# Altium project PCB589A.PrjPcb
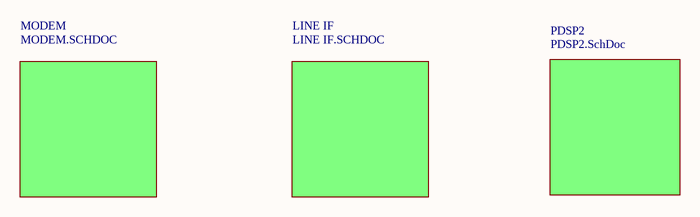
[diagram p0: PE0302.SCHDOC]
AAProductName: PE0302-; AABoardName: PCB589A
5 sheets, 127 parts. Net scope: flat (ports and power ports of the same name join across sheets).
Board file: PCB589A.PcbDoc
Sheets:
  FS.SchDoc
  PE0302.SCHDOC
    MODEM = MODEM.SCHDOC
    LINE IF = LINE IF.SCHDOC
    PDSP2 = PDSP2.SchDoc

## Sheet FS.SchDoc
size A3; Author: A.A.; Organization: CML Microcircuits UK Ltd; Address1: Oval Park, Langford; Address2: Maldon, Essex; Address3: CM9 6WG, England; DocumentNumber: 1; Revision: A01; SheetNumber: 1; SheetTotal: 5; FSProduct: PE0302; FSIPRDate: 2014; FSUM: UM/0302/1; FSDate: Dec 2014

## Sheet PE0302.SCHDOC: PE0302 - PDSP2 Evaluation Board
size A2; Date: /04/2011; DrawnBy: PB; Engineer: PB; Revision: A.01; SheetNumber: 5; SheetTotal: 5; ModifiedBy: PB; ProjectNo: 589

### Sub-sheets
LINE IF = LINE IF.SCHDOC: no entries
MODEM = MODEM.SCHDOC: no entries
PDSP2 = PDSP2.SchDoc: no entries

## Sheet MODEM.SCHDOC: PE0302 - PDSP2 Evaluation Board
size A2; Date: /04/2011; DrawnBy: PB; Engineer: PB; Organization: CML Microcircuits UK Ltd; Address1: Oval Park, Langford; Address2: Maldon, Essex; Address3: CM9 6WG, England; DocumentNumber: 2; Revision: A.01; SheetNumber: 2; SheetTotal: 5; ModifiedBy: PB; ProjectNo: 589
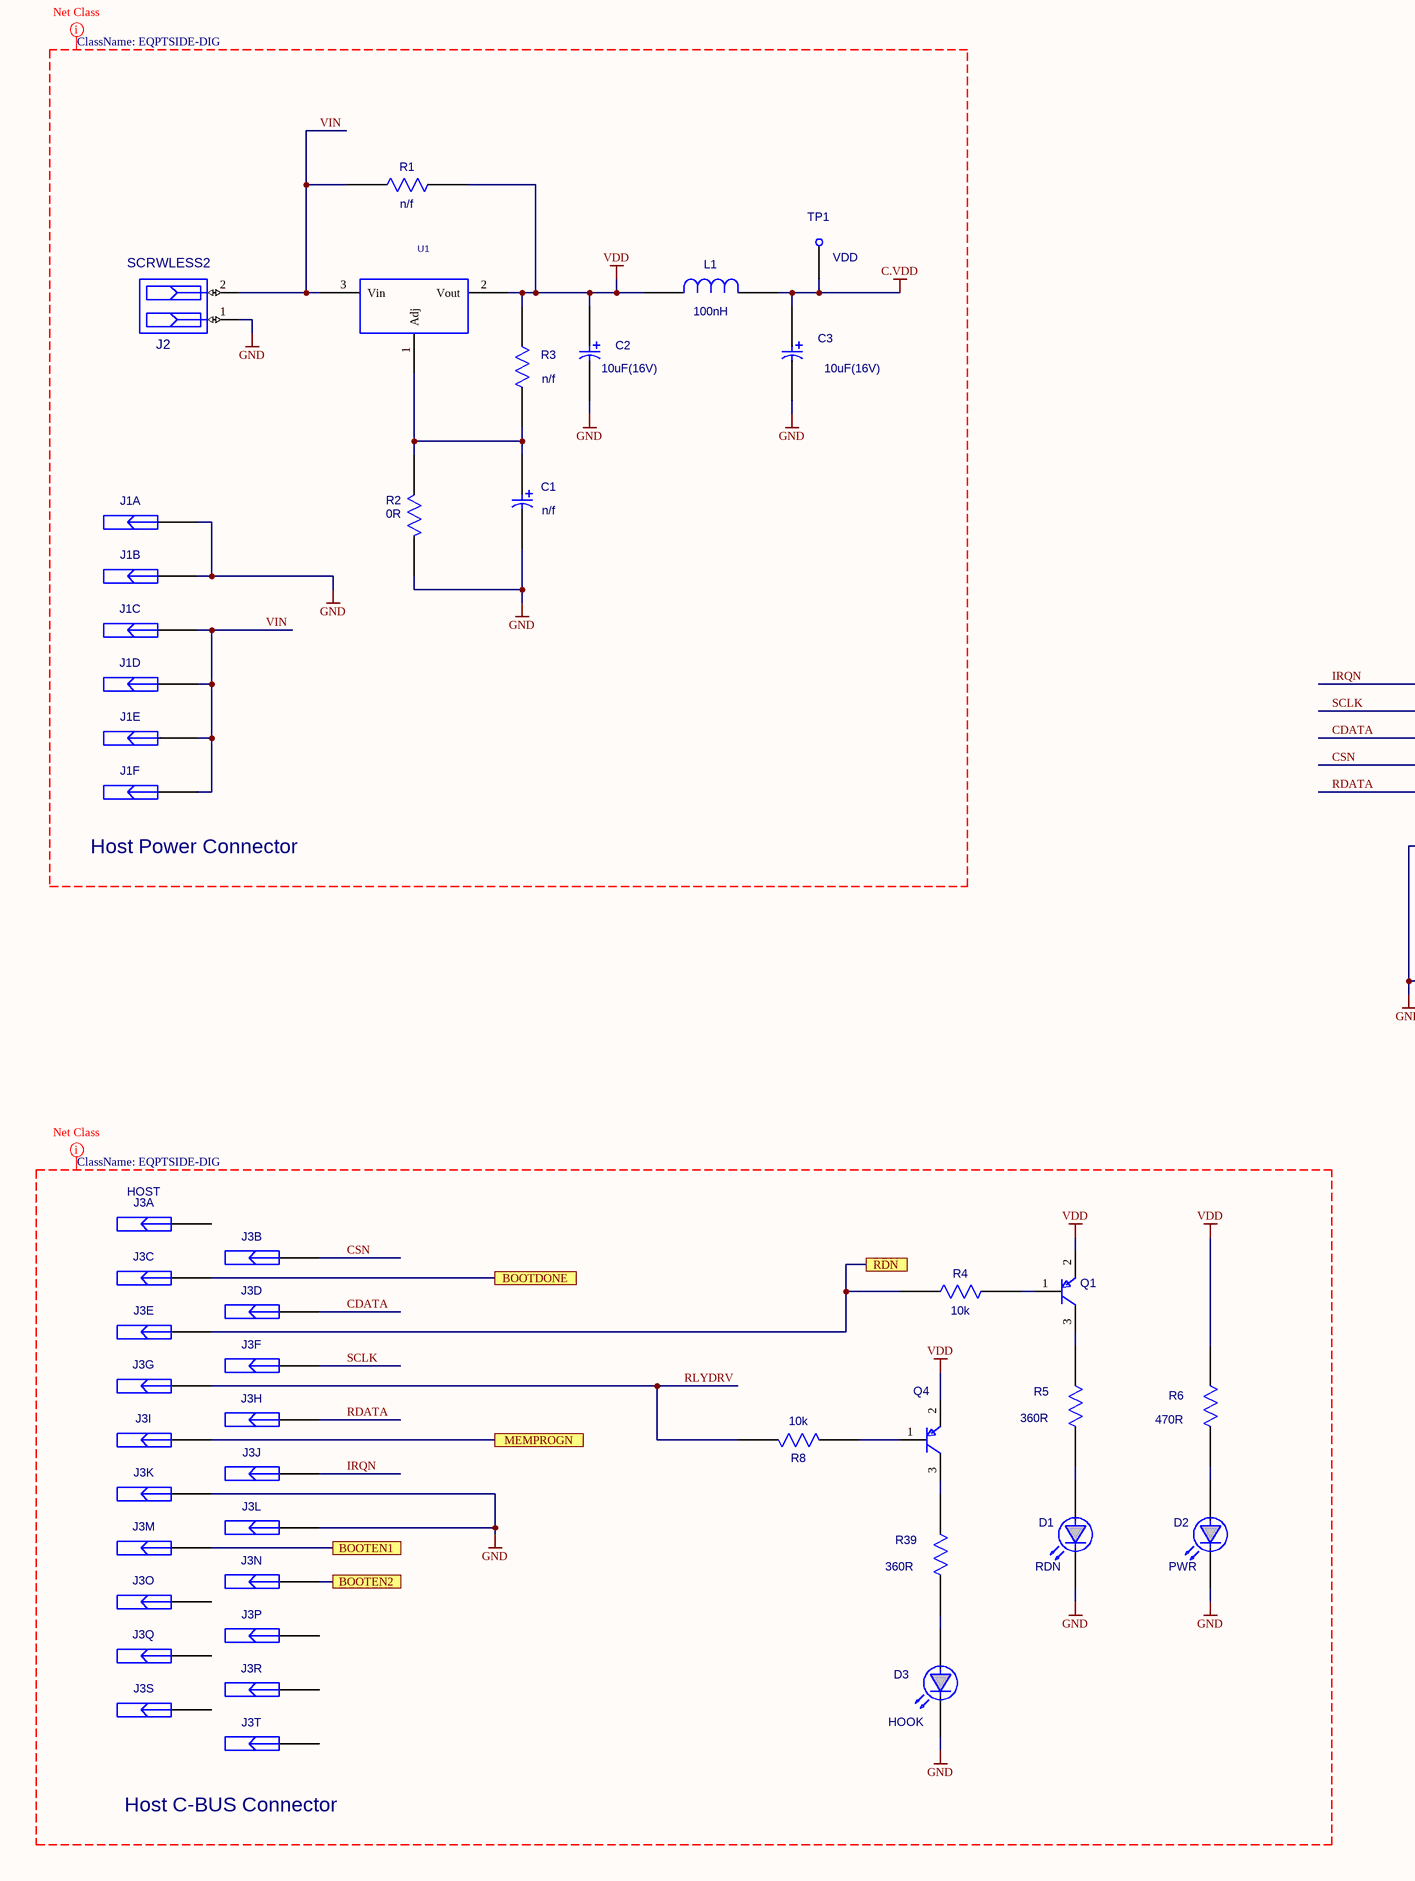
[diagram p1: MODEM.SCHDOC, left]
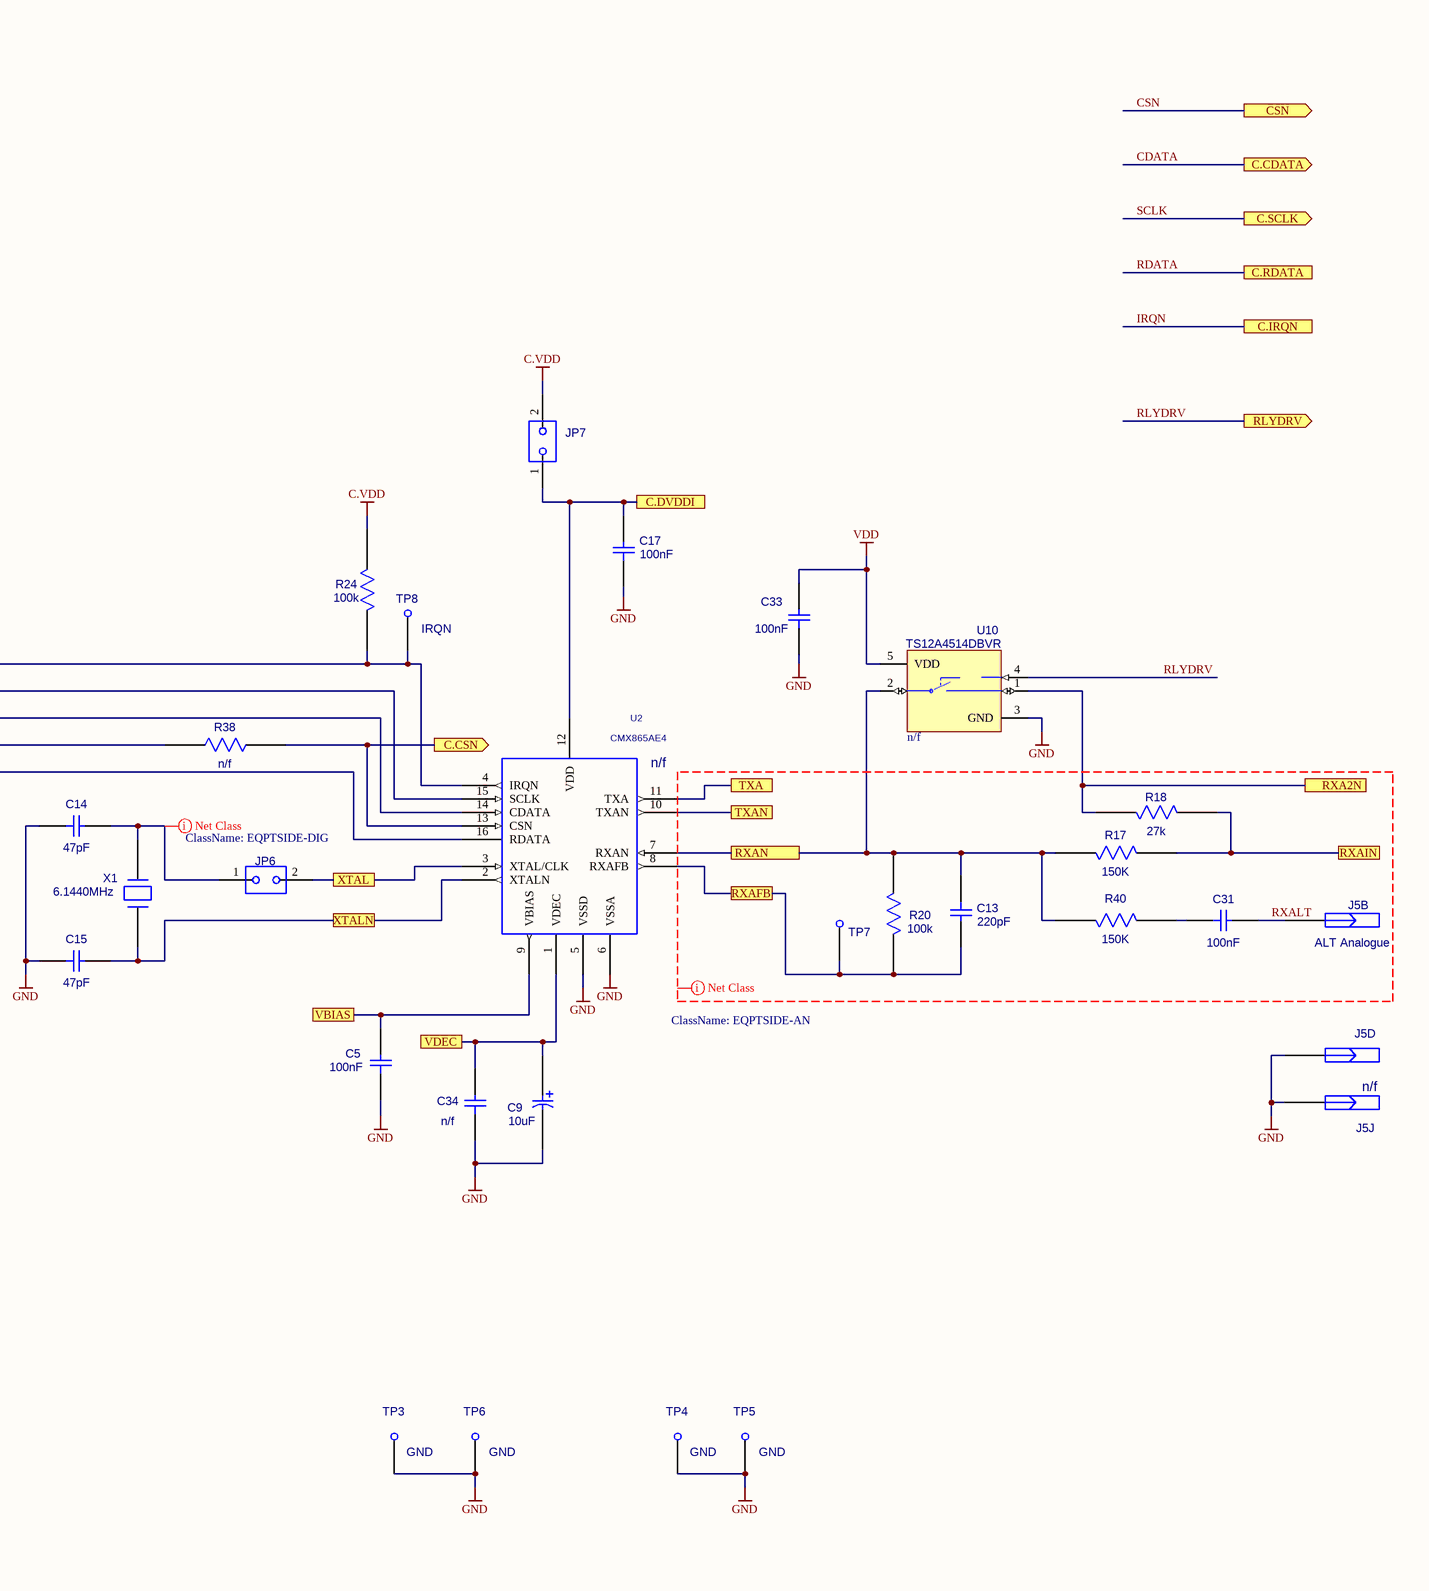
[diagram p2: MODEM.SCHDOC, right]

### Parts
C1  n/f  [TC3528P_CAP_TANT_TAJ_B(Primary)]
C2  10uF(16V)  [TC3528P_CAP_TANT_TAJ_B(Primary)]
C3  10uF(16V)  [TC3528P_CAP_TANT_TAJ_B(Primary)]
C5  100nF  [0603COM]
C9  10uF  [TC3528P_CAP_TANT_TAJ_B(Primary)]
C13  220pF  [0603COM]
C14  47pF  [0603COM]
C15  47pF  [0603COM]
C17  100nF  [0603COM]
C31  100nF  [0603COM]
C33  100nF  [0603COM]
C34  n/f  [0603COM]
D1  RDN  [LED0805]
D2  PWR  [LED0805]
D3  HOOK  [LED0805]
J1  (no value)  [IDC6RM]  (parts A,B,C,D,E,F of 6)
J2  SCRWLESS2  [SCRWLESS_2]
J3  HOST  [IDC20RM]  (parts A,B,C,D,E,F,G,H,I,J,K,L,M,N,O,P,Q,R,S,T of 20)
J5  ALT Analogue  [IDC10M]  (parts B,D,J of 10)
JP6  (no value)  [JMP2]
JP7  (no value)  [JMP2]
L1  100nH  [RC0805]
Q1  (no value)  [SOT-23]
Q4  (no value)  [SOT-23]
R1  n/f  [RC0805]
R2  0R  [0603COM]
R3  n/f  [RC0805]
R4  10k  [0603COM]
R5  360R  [0603COM]
R6  470R  [0603COM]
R8  10k  [0603COM]
R17  150K  [0603COM]
R18  27k  [0603COM]
R20  100k  [0603COM]
R24  100k  [0603COM]
R38  n/f  [0603COM]
R39  360R  [0603COM]
R40  150K  [0603COM]
TP1  VDD  [FISH_BEAD_FOOT_FISH_BEAD(Primary)]
TP3  GND  [FISH_BEAD_FOOT_FISH_BEAD(Primary)]
TP4  GND  [FISH_BEAD_FOOT_FISH_BEAD(Primary)]
TP5  GND  [FISH_BEAD_FOOT_FISH_BEAD(Primary)]
TP6  GND  [FISH_BEAD_FOOT_FISH_BEAD(Primary)]
TP7  RXAFB  [FISH_BEAD_FOOT_FISH_BEAD(Primary)]  (value not drawn)
TP8  IRQN  [FISH_BEAD_FOOT_FISH_BEAD(Primary)]
U1  (no value)  [TO-252]
U2  CMX865AE4  value n/f  [E4]
U10  TS12A4514DBVR  value n/f  [SOT23-5]
X1  6.1440MHz  [HC49]

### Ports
BOOTDONE, BOOTEN1, BOOTEN2, C.CDATA (out), C.CSN (out), C.DVDDI, C.IRQN, C.RDATA, C.SCLK (out), CSN (out), MEMPROGN, RDN, RLYDRV (out), RXA2N, RXAFB, RXAIN, RXAN, TXA, TXAN, VBIAS, VDEC, XTAL, XTALN

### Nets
C.VDD: C3.A(+ve) JP7.2 L1.1 R24.1 TP1.TP
GND: C1.B(-ve) C2.B(-ve) C3.B(-ve) C5.1 C9.B(-ve) C14.1 C15.1 C17.1 C33.1 C34.1 D1.2(CATHODE) D2.2(CATHODE) D3.2(CATHODE) J1.1 J1.2 J2.1 J3.11 J3.12 J5.4(P1) J5.10(P1) R2.1 TP3.TP TP4.TP TP5.TP TP6.TP U2.5(VSSD) U2.6(VSSA) U10.3(GND)
VDD: C2.A(+ve) C33.2 L1.2 Q1.2(E) Q4.2(E) R1.2 R3.2 R6.2 U1.2(Vout) U10.5(VDD)
BOOTDONE: J3.3 ; port BOOTDONE
BOOTEN1: J3.13 ; port BOOTEN1
BOOTEN2: J3.14 ; port BOOTEN2
C.CSN: R38.2 U2.13(CSN) ; port C.CSN
C.DVDDI: C17.2 JP7.1 U2.12(VDD) ; port C.DVDDI
CDATA: J3.4 U2.14(CDATA) ; port C.CDATA
CSN: J3.2 R38.1 ; port CSN
IRQN: J3.10 R24.2 TP8.TP U2.4(IRQN) ; port C.IRQN
MEMPROGN: J3.9 ; port MEMPROGN
NET00027: R18.2 U10.1(COM) ; port RXA2N
RDATA: J3.8 U2.16(RDATA) ; port C.RDATA
RDN: J3.5 R4.1 ; port RDN
RLYDRV: J3.7 R8.1 U10.4(IN) ; port RLYDRV
RXAFB: C13.2 R20.2 TP7.TP U2.8(RXAFB) ; port RXAFB
RXAIN: R17.1 R18.1 ; port RXAIN
RXALT: C31.2 J5.2(P1)
RXAN: C13.1 R17.2 R20.1 R40.2 U2.7(RXAN) U10.2(NO) ; port RXAN
SCLK: J3.6 U2.15(SCLK) ; port C.SCLK
TXA: U2.11(TXA) ; port TXA
TXAN: U2.10(TXAN) ; port TXAN
VBIAS: C5.2 U2.9(VBIAS) ; port VBIAS
VDEC: C9.A(+ve) C34.2 U2.1(VDEC) ; port VDEC
VIN: J1.3 J1.4 J1.5 J1.6 J2.2 R1.1 U1.3(Vin)
XTAL: JP6.2 U2.3(XTAL/CLK) ; port XTAL
XTALN: C15.2 U2.2(XTALN) X1.1 ; port XTALN
NetC1_A: C1.A(+ve) R2.2 R3.1 U1.1(Adj)
NetC14_2: C14.2 JP6.1 X1.2
NetC31_1: C31.1 R40.1
NetD1_1: D1.1(ANODE) R5.1
NetD2_1: D2.1(ANODE) R6.1
NetD3_1: D3.1(ANODE) R39.1
NetQ1_1: Q1.1(B) R4.2
NetQ1_3: Q1.3(C) R5.2
NetQ4_1: Q4.1(B) R8.2
NetQ4_3: Q4.3(C) R39.2

Not connected (* = marked no-connect by the designer): J3 1 15 16 17 18 19 20

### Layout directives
net class EQPTSIDE-DIG: C.VDD, CDATA, CSN, GND, IRQN, NetC14_2, RDATA, RLYDRV, SCLK, VDD, VIN
net class EQPTSIDE-AN: RXALT

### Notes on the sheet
- (near J1) Host Power Connector
- (near J3) Host C-BUS Connector

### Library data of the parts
C1-C3 C9 = CAP_TANT_TAJ_B: TAJ series case code B, SMT tantalum; Part Number: CAP095; WhenFit: SMT_CAP
C5 C17 C31 C33 = CAP0603: SMT capacitor; Part Number: CAP062; WhenFit: SMT_CAP
C13 = CAP0603: SMT capacitor; Part Number: CAP066; WhenFit: SMT_CAP
C14 C15 = CAP0603: SMT capacitor; Part Number: CAP088; WhenFit: SMT_CAP
C34 = CAP0603: SMT capacitor; Part Number: CAP141; WhenFit: SMT_CAP
D1-D3 = LED0805: LED, 0805 surface mount; Part Number: OPT005; WhenFit: SMT_Other
J1 = HEADER_2*3RM: 3 + 3 double row 0.1in header right angle; Part Number: CON082; WhenFit: PTH
J2 = SCRWLESS2: 2-way Screwless Terminal Block; Part Number: CON083; Value: Rapid 21-2626
J3 = HEADER_2*10RM: 10 + 10 double row 0.1in header right angle; Part Number: CON057; WhenFit: PTH
J5 = HEADER_2*5: 10 way, 0.1inch pitch header; Part Number: CON027; Value: n/f; WhenFit: PTH
JP6 JP7 = JUMPER2: PIN HEADER 2X1; Part Number: CON005; WhenFit: PTH
L1 = IND0805: SMT Inductor; Part Number: TRF003; WhenFit: SMT_Other
Q1 Q4 = BC856: General purpose transistor PNP SMT; Part Number: DSM055; OriginalName: BC856BLT1; ComponentField7: Published 29-Sep-2000; WhenFit: SMT_Other
R1 = CRG0805: Generic SMT resistor, 1%.0.125W.; Part Number: RES076; WhenFit: SMT_RES
R2 = CRG0603: Generic SMT resistor, 1%.0.1W.; Part Number: RES135; WhenFit: SMT_RES
R3 = CRG0805: Generic SMT resistor, 1%.0.125W.; Part Number: {Part Number}; WhenFit: SMT_RES
R4 R8 = CRG0603: Generic SMT resistor, 1%.0.1W.; Part Number: RES065; WhenFit: SMT_RES
R5 R39 = CRG0603: Generic SMT resistor, 1%.0.1W.; Part Number: RES154; WhenFit: SMT_RES
R6 = CRG0603: Generic SMT resistor, 1%.0.1W.; Part Number: RES168; WhenFit: SMT_RES
R17 R40 = CRG0603: Generic SMT resistor, 1%.0.1W.; Part Number: RES148; WhenFit: SMT_RES
R18 = CRG0603: Generic SMT resistor, 1%.0.1W.; Part Number: RES139; WhenFit: SMT_RES
R20 R24 = CRG0603: Generic SMT resistor, 1%.0.1W.; Part Number: RES066; WhenFit: SMT_RES
R38 = CRG0603: Generic SMT resistor, 1%.0.1W.; Part Number: {Part Number}; WhenFit: SMT_RES
TP1 TP3-TP6 = FISH_BEAD: Fish Beads 1.32mm PCB hole; Part Number: CON008; WhenFit: PTH
TP7 = FISH_BEAD: Fish Beads 1.32mm PCB hole; Part Number: CON008; silkscreen label: {silkscreen label}; FitAfterWash: FALSE
TP8 = FISH_BEAD: Fish Beads 1.32mm PCB hole; Part Number: CON008
U1 = LM1117-ADJ-TO-252: Part Number: ICS100; WhenFit: SMT_Other
U2 = CMX865AE4: Telecom Signalling Device; WhenFit: {WhenFit}
U10 = TS12A4514DBVR: TI, SPST, CMOS analogue switch, surface mount SOT23-5; Part Number: ICS124; WhenFit: {WhenFit}
X1 = XTAL-HC49: HC49 Xtal; Part Number: XTL022; WhenFit: AWASH

## Sheet LINE IF.SCHDOC: PE0302 - PDSP2 Evaluation Board
size A2; Date: /04/2011; DrawnBy: PB; Engineer: PB; DocumentNumber: 4; Revision: A.01; SheetNumber: 3; SheetTotal: 5; ModifiedBy: PB; ProjectNo: 589
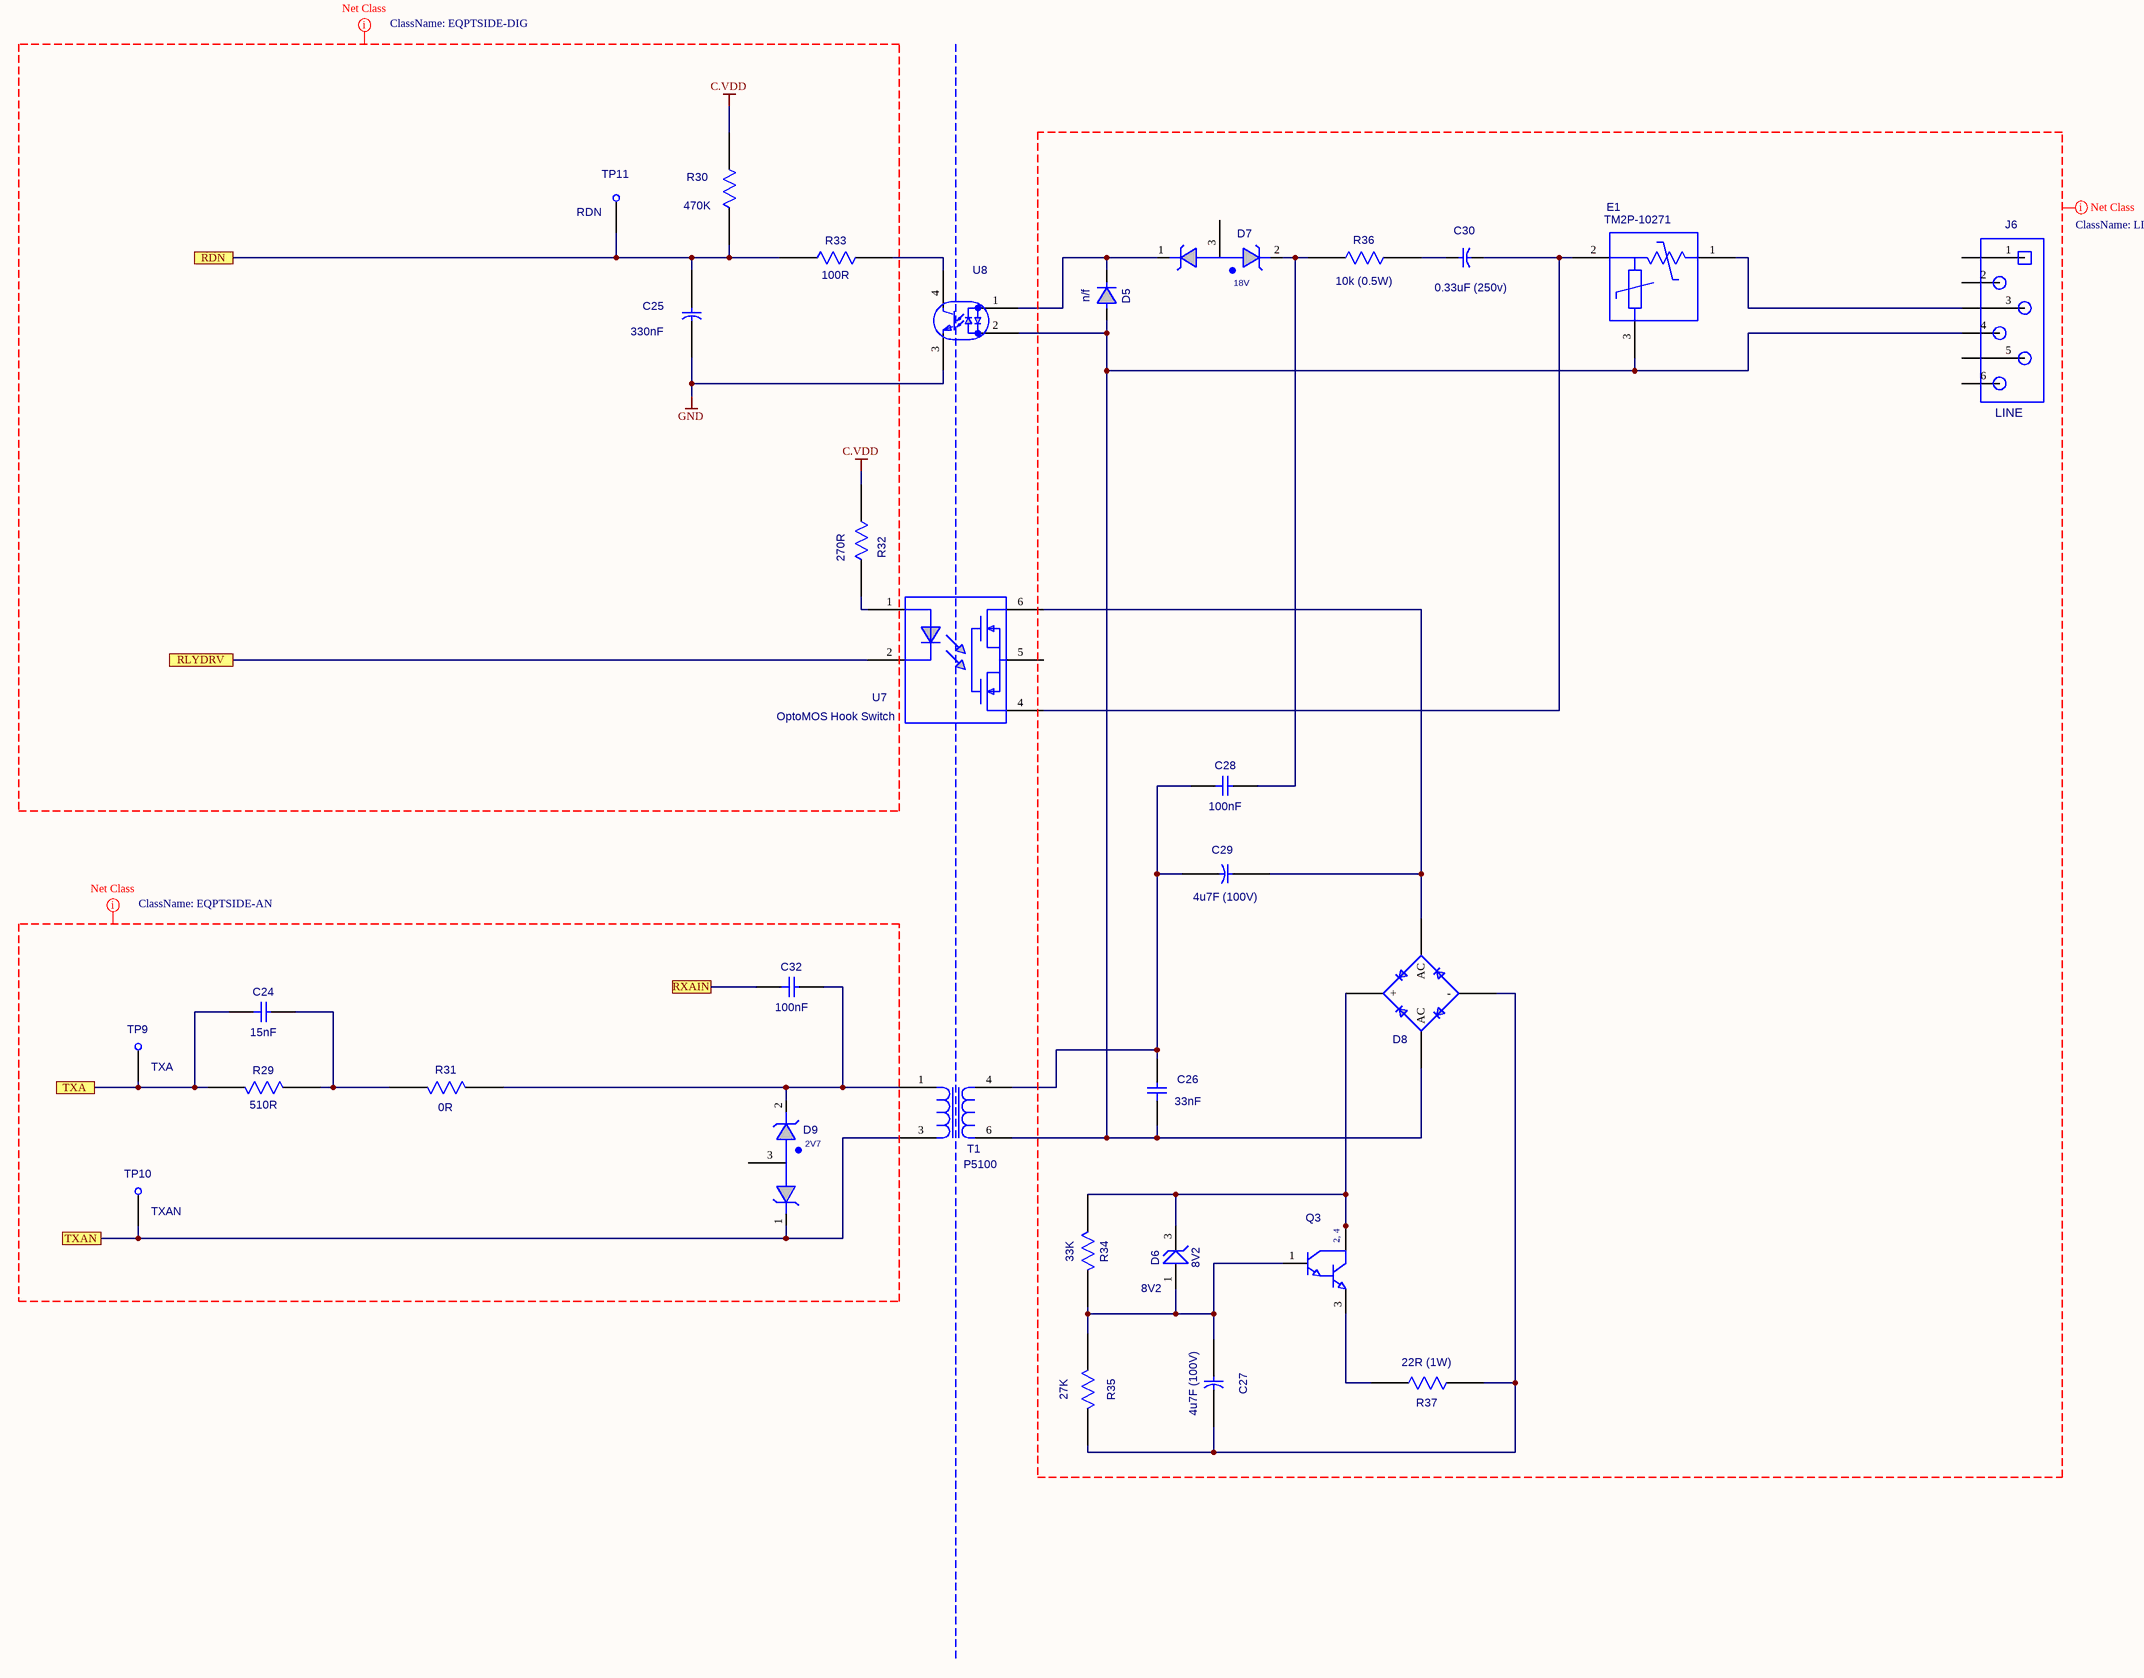
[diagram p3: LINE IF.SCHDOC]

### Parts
C24  15nF  [0603COM]
C25  330nF  [CC0805]
C26  33nF  [0603COM]
C27  4u7F (100V)  [CAP100R]
C28  100nF  [0603COM]
C29  4u7F (100V)  [CAP100R]
C30  0.33uF (250v)  [CC1812]
C32  100nF  [0603COM]
D5  n/f  [SOT23(SDG)]
D6  8V2  [SO-G3/Z3.3]
D7  18V  [SOT23(SDG)]
D8  (no value)  [SDIP4]
D9  2V7  [SOT23(SDG)]
E1  TM2P-10271  [TM2PRO]
J6  LINE  [RJ11SKT_RJ11SKT(Primary)]
Q3  (no value)  [DSO-G3/D7]
R29  510R  [0603COM]
R30  470K  [RC0805]
R31  0R  [0603COM]
R32  270R  [RC0805]
R33  100R  [0603COM]
R34  33K  [0603COM]
R35  27K  [0603COM]
R36  10k (0.5W)  [RC12181WA]
R37  22R (1W)  [RC12181WA]
T1  P5100  [LINEXFMR_XFMR_LINE(Primary)]
TP9  TXA  [FISH_BEAD_FOOT_FISH_BEAD(Primary)]
TP10  TXAN  [FISH_BEAD_FOOT_FISH_BEAD(Primary)]
TP11  RDN  [FISH_BEAD_FOOT_FISH_BEAD(Primary)]
U7  (no value)  [SMD6]
U8  (no value)  [SOP4]

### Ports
RDN, RLYDRV, RXAIN, TXA, TXAN

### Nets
C.VDD: R30.2 R32.1
GND: C25.1 U8.3(e)
RDN: C25.2 R30.1 R33.1 TP11.TP ; port RDN
RLYDRV: U7.2 ; port RLYDRV
RXAIN: C32.1 ; port RXAIN
TXA: C24.1 R29.2 TP9.TP ; port TXA
TXAN: D9.1(C2) T1.3 TP10.TP ; port TXAN
NetC24_2: C24.2 R29.1 R31.2
NetC26_1: C26.1 D5.1(A) D8.3(AC) E1.3 J6.4 T1.6 U8.2
NetC26_2: C26.2 C28.1 C29.1 T1.4
NetC27_1: C27.1 D8.2(-) R35.2 R37.2
NetC27_2: C27.2 D6.1(A) Q3.1(B) R34.1 R35.1
NetC28_2: C28.2 D7.2(C1) R36.1
NetC29_2: C29.2 D8.4(AC) U7.6
NetC30_1: C30.1 E1.2 U7.4
NetC30_2: C30.2 R36.2
NetC32_2: C32.2 D9.2(C1) R31.1 T1.1
NetD5_3: D5.3(K) D7.1(C2) U8.1
NetD6_3: D6.3(K) D8.1(+) Q3.2(C) Q3.4(C) R34.2
NetE1_1: E1.1 J6.3
NetQ3_3: Q3.3(E) R37.1
NetR32_2: R32.2 U7.1
NetR33_2: R33.2 U8.4(c)

Not connected (* = marked no-connect by the designer): D5 2; D7 3(A1A2); D9 3(A1A2); J6 1 2 5 6 dummy1 dummy2; U7 3(NC) 5

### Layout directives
net class LINESIDE: (no net found under the mark)
net class EQPTSIDE-DIG: C.VDD, GND
net class EQPTSIDE-AN: (no net found under the mark)

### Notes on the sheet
- (near U7) OptoMOS Hook Switch

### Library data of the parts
C24 = CAP0603: SMT capacitor; Part Number: CAP122; WhenFit: SMT_CAP
C25 = CAP0805: SMT capacitor; Part Number: CAP092; WhenFit: SMT_CAP
C26 = CAP0603: SMT capacitor; Part Number: CAP093; WhenFit: SMT_CAP
C27 C29 = CAP100R: Non-polarised radial capacitor 100 thou pin spacing.; Part Number: CAP053; WhenFit: AWASH
C28 C32 = CAP0603: as C5 on sheet MODEM
C30 = CAP1812: Generic capacitor, surface mount 1812; Part Number: CAP090; WhenFit: SMT_CAP
D5 = BAS16: Switching diode, surface mount SOT-23; Part Number: DSM022; WhenFit: SMT_Other
D6 = BZX84: BZX series zener 300mW SMT; Part Number: DSM046; OriginalName: BZX84C10LT1; ComponentField6: Pin 2 is not connected and not drawn.; ComponentField7: Published 29-Sep-2000; WhenFit: SMT_Other
D7 = CMPZDA: Dual Zener diode, common anode, SOT-23; Part Number: DSM063; WhenFit: SMT_Other
D8 = CBRHD-02: Central Semiconductor surface mount bridge rectifier, 0.5A; Part Number: DSM029; WhenFit: SMT_Other
D9 = CMPZDA: Dual Zener diode, common anode, SOT-23; Part Number: DSM064; WhenFit: SMT_Other
E1 = TM2PRO: 2Pro Integrated overcurrent/overvoltage protection device; Part Number: FUS003; WhenFit: PTH
J6 = RJ11SKT: RJ11 telephone socket; Part Number: CON014; WhenFit: PTH
Q3 = CZT2000: NPN Darlington 2W SOT223; Part Number: DSM045; OriginalName: FZT605; WhenFit: SMT_Other
R29 = CRG0603: Generic SMT resistor, 1%.0.1W.; Part Number: RES151; WhenFit: SMT_RES
R30 = CRG0805: Generic SMT resistor, 1%.0.125W, RS CRG0805 series.; Part Number: RES096; WhenFit: SMT_RES
R31 = CRG0603: as R2 on sheet MODEM
R32 = CRG0805: Generic SMT resistor, 1%.0.125W, RS CRG0805 series.; Part Number: RES069; WhenFit: SMT_RES
R33 = CRG0603: Generic SMT resistor, 1%.0.1W.; Part Number: RES067; WhenFit: SMT_RES
R34 = CRG0603: Generic SMT resistor, 1%.0.1W.; Part Number: RES147; WhenFit: SMT_RES
R35 = CRG0603: as R18 on sheet MODEM
R36 = RC12181W: Philips Components 1W, SMT 1218  resistor; Part Number: RES104; WhenFit: SMT_RES
R37 = RC12181W: Philips Components 1W, SMT 1218  resistor; Part Number: RES150; WhenFit: SMT_RES
T1 = XFMR_LINE: 600R line transformer; Part Number: TRF024; WhenFit: AWASH
TP9-TP11 = FISH_BEAD: as TP1 on sheet MODEM
U7 = LCA110S: Single pole optoMOS relay; Part Number: ICS034; WhenFit: SMT_Other
U8 = PC354NT: AC input photocoupler; Part Number: ICS036; WhenFit: SMT_Other

## Sheet PDSP2.SchDoc: PE0302 - PDSP2 Evaluation Board
size A2; Date: /04/2011; Author: A.A.; DrawnBy: PB; Engineer: PB; Organization: CML Microcircuits UK Ltd; Address1: Oval Park, Langford; Address2: Maldon, Essex; Address3: CM9 6WG, England; Revision: A.01; SheetNumber: 4; SheetTotal: 5; ModifiedBy: PB; ProjectNo: 589
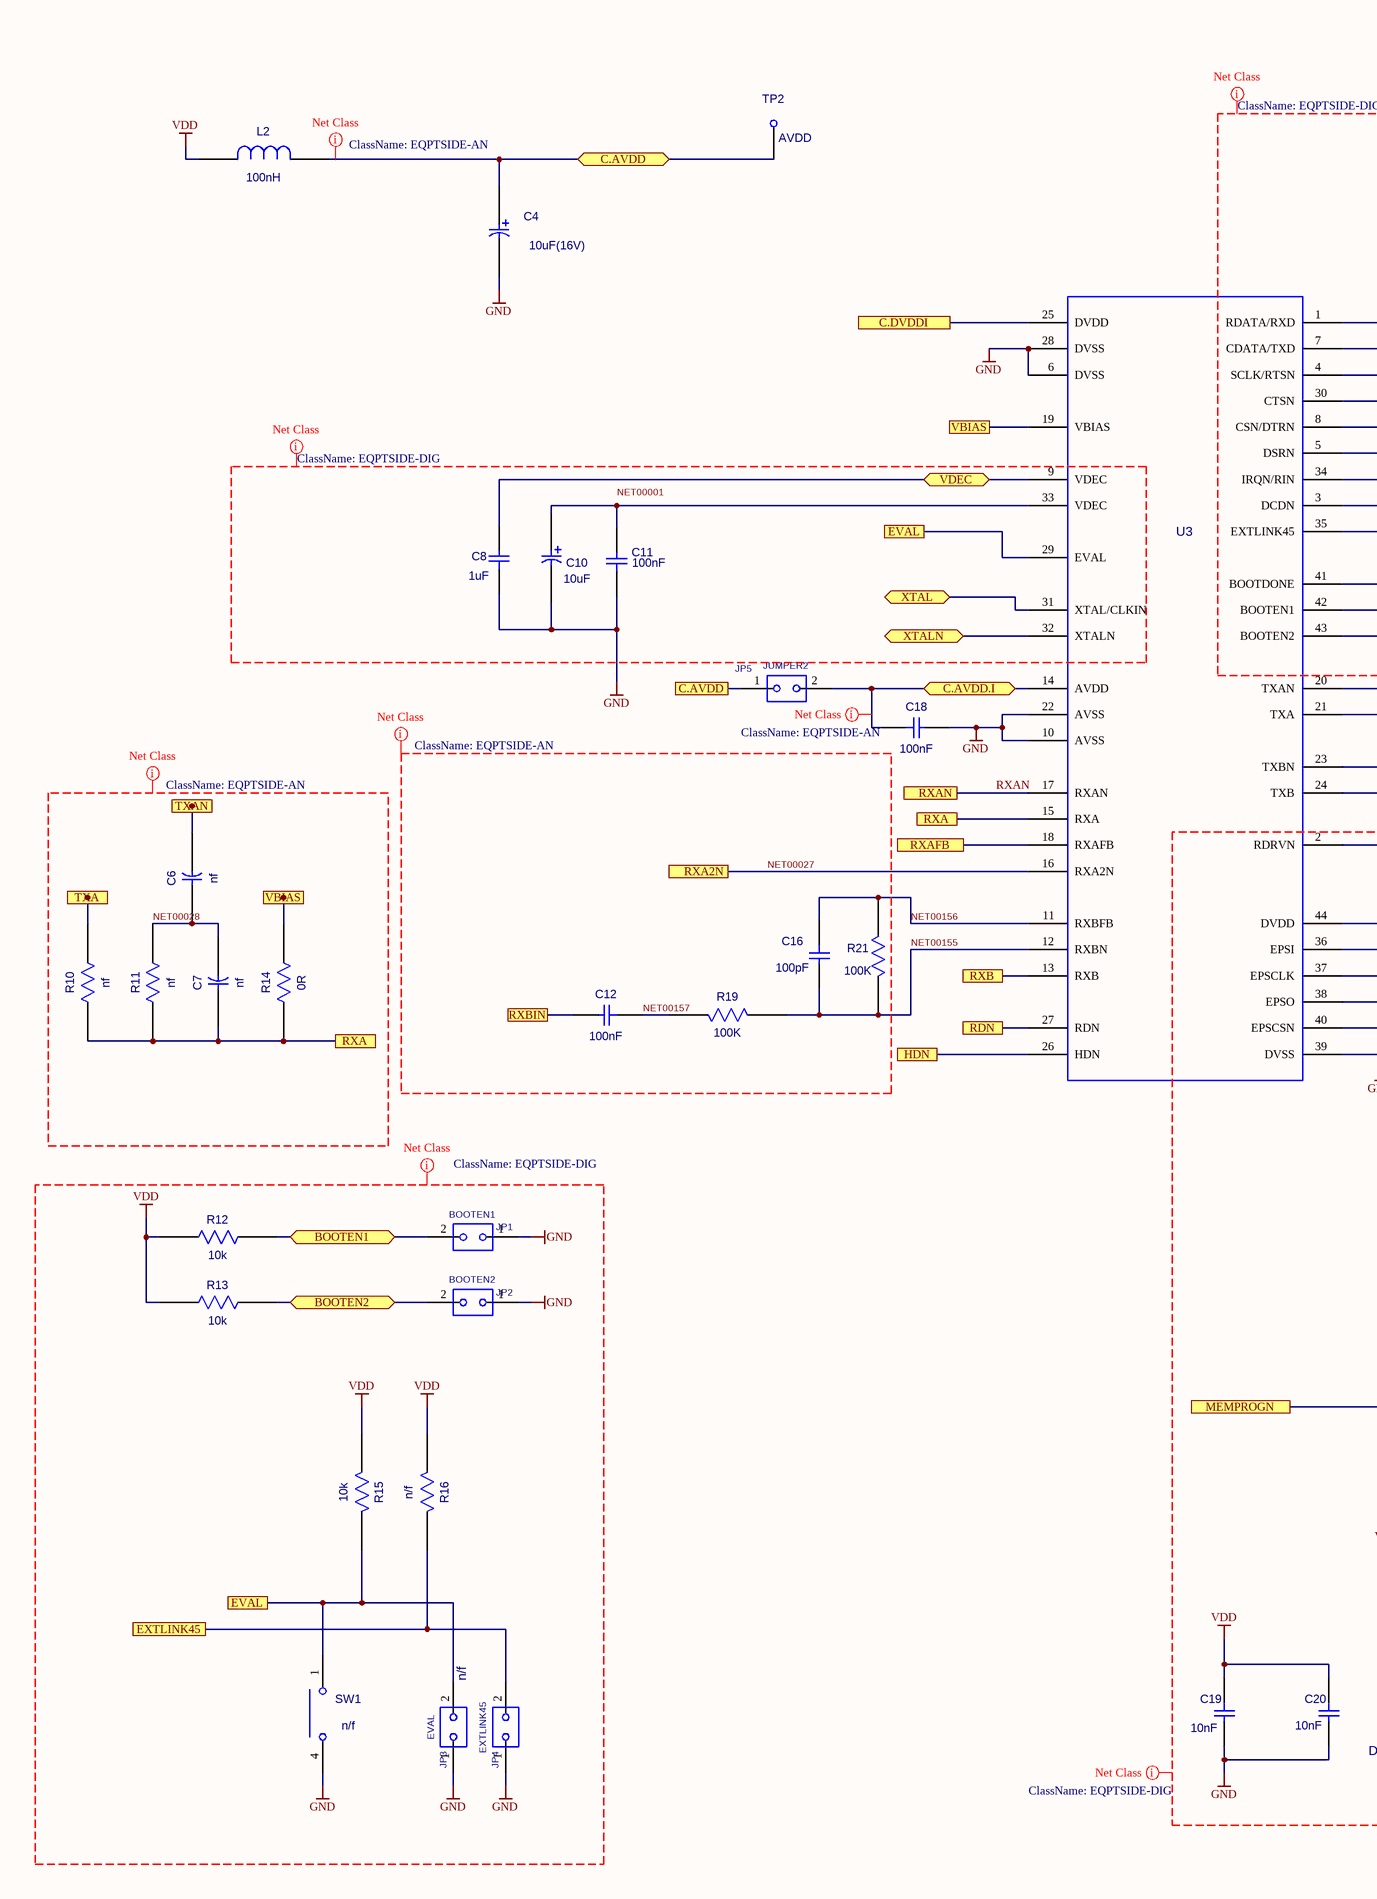
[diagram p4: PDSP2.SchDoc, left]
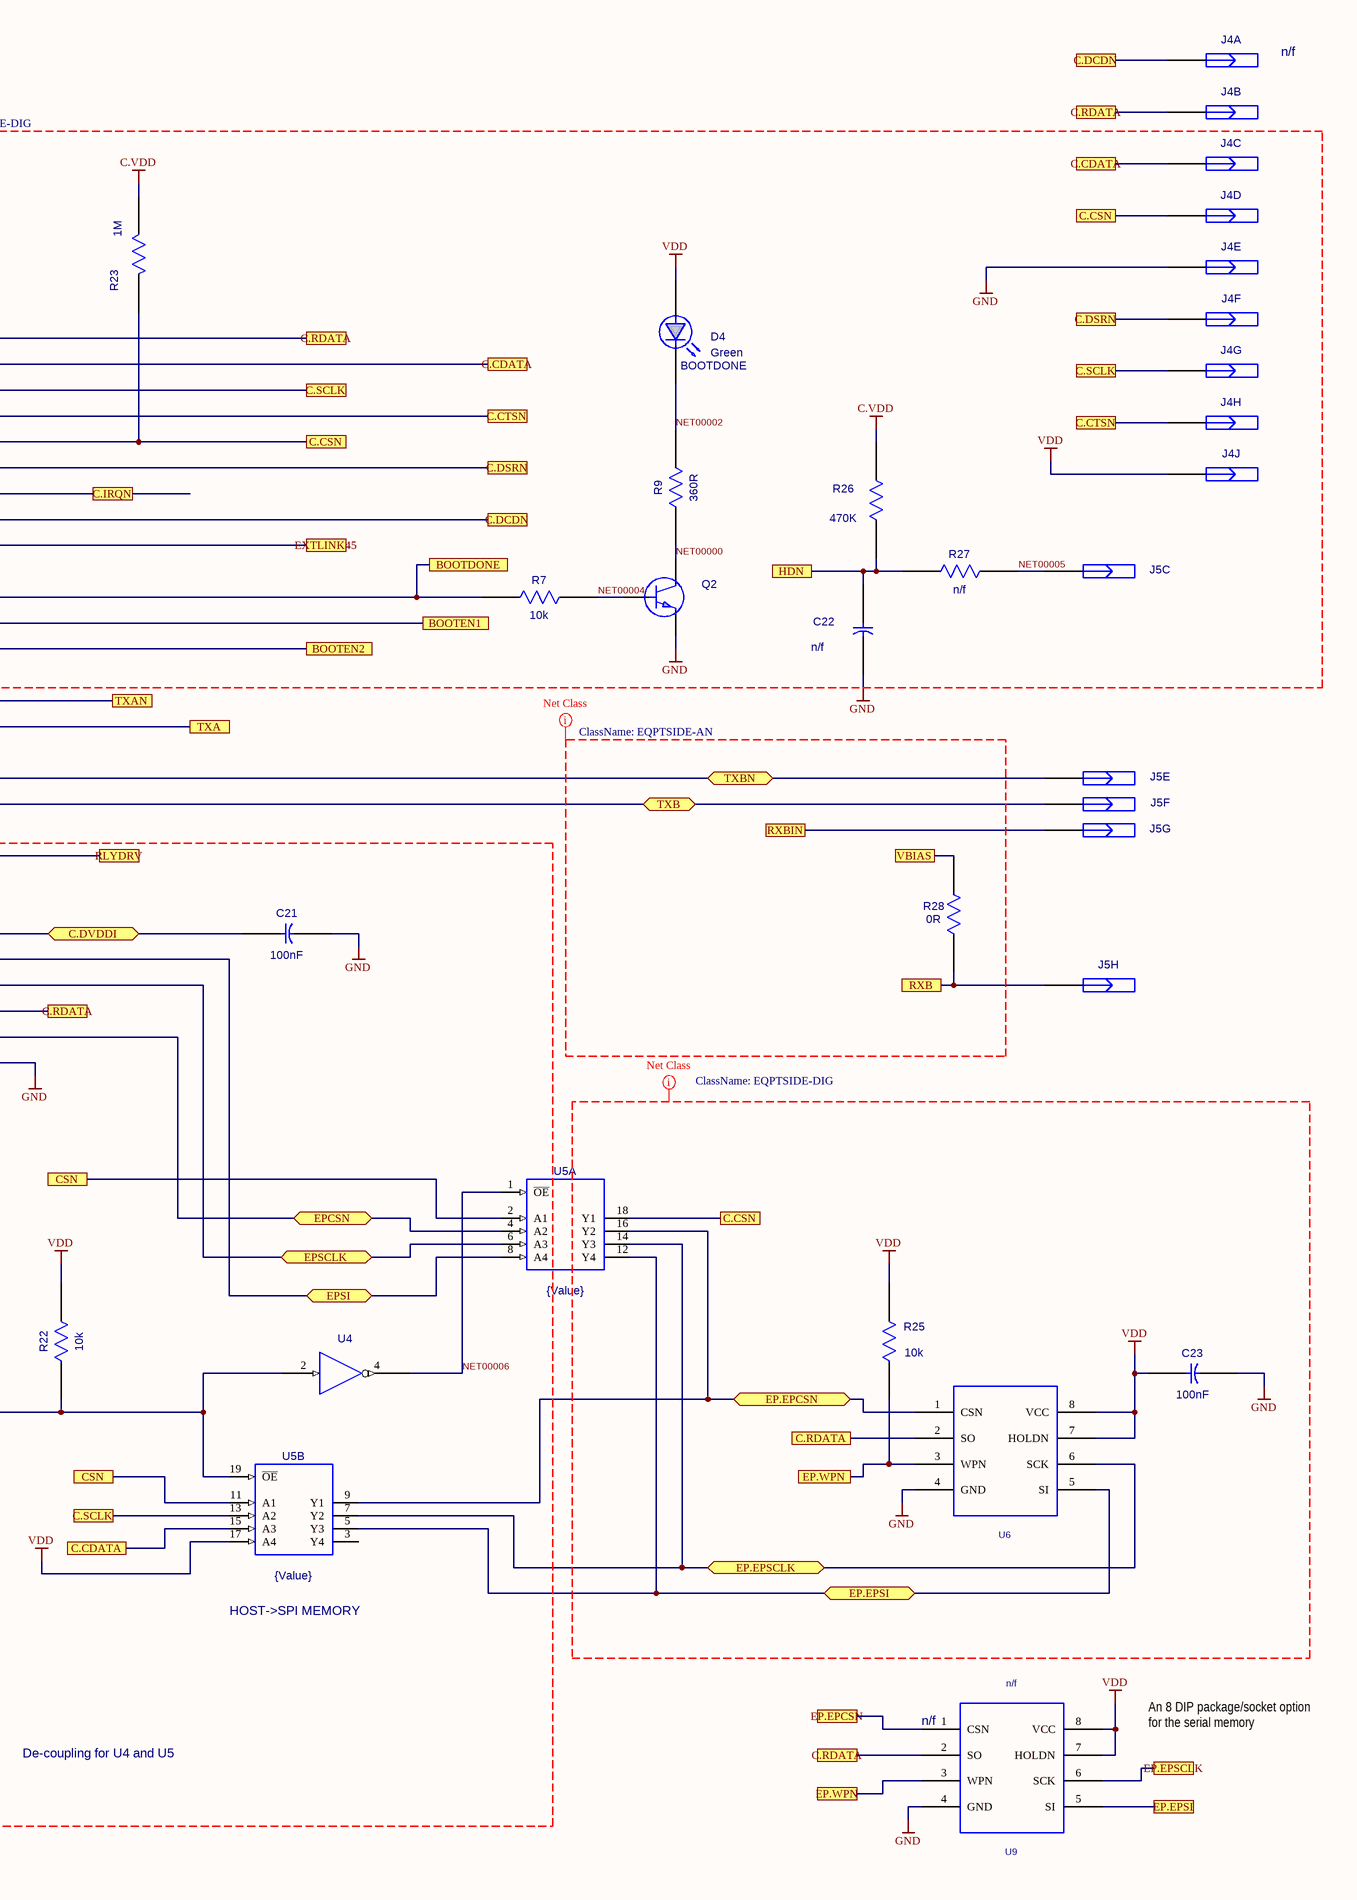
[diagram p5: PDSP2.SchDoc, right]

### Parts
C4  10uF(16V)  [TC3528P_CAP_TANT_TAJ_B(Primary)]
C6  nf  [CC0805]
C7  nf  [CC0805]
C8  1uF  [0603COM]
C10  10uF  [TC3528P_CAP_TANT_TAJ_B(Primary)]
C11  100nF  [0603COM]
C12  100nF  [0603COM]
C16  100pF  [0603COM]
C18  100nF  [0603COM]
C19  10nF  [0603COM]
C20  10nF  [0603COM]
C21  100nF  [CC0805]
C22  n/f  [CC0805]
C23  100nF  [CC0805]
D4  BOOTDONE  value Green  [LED0805]
J4  n/f  [IDC10M]  (parts A,B,C,D,E,F,G,H,J of 10)
J5  n/f  [IDC10M]  (value not drawn)  (parts C,E,F,G,H of 10)
JP1  BOOTEN1  [JMP2]
JP2  BOOTEN2  [JMP2]
JP3  EVAL  value n/f  [JMP2]
JP4  EXTLINK45  [JMP2]
JP5  JUMPER2  [JMP2]
L2  100nH  [RC0805]
Q2  (no value)  [SOT23(SDG)_BC846(Primary)]
R7  10k  [0603COM]
R9  360R  [0603COM]
R10  nf  [RC0805]
R11  nf  [RC0805]
R12  10k  [RC0805]
R13  10k  [RC0805]
R14  0R  [RC0805]
R15  10k  [RC0805]
R16  n/f  [RC0805]
R19  value 100K  [0603COM]  (hidden comment: 150K)
R21  value 100K  [0603COM]  (hidden comment: 150K)
R22  10k  [0603COM]
R23  1M  [RC0805]
R25  10k  [RC0805]
R26  470K  [RC0805]
R27  n/f  [RC0805]
R28  0R  [0603COM]
SW1  n/f  [OMRONB3SN]
TP2  AVDD  [FISH_BEAD_FOOT_FISH_BEAD(Primary)]
U3  (no value)  [PLCCSOCKET44]
U4  (no value)  [SOT23-5]
U5  value {Value}  [SO-G20]  (parts A,B of 2)
U6  (no value)  [DIP8]
U9  n/f  [SO8]

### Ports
BOOTDONE, BOOTEN1, BOOTEN1 (bidir), BOOTEN2, BOOTEN2 (bidir), C.AVDD, C.AVDD (bidir), C.AVDD.I (bidir), C.CDATA, C.CSN, C.CTSN, C.DCDN, C.DSRN, C.DVDDI, C.DVDDI (bidir), C.IRQN, C.RDATA, C.SCLK, CSN, EP.EPCSN, EP.EPCSN (bidir), EP.EPSCLK, EP.EPSCLK (bidir), EP.EPSI, EP.EPSI (bidir), EP.WPN, EPCSN (bidir), EPSCLK (bidir), EPSI (bidir), EVAL, EXTLINK45, HDN, MEMPROGN, RDN, RLYDRV, RXA, RXA2N, RXAFB, RXAN, RXB, RXBIN, TXA, TXAN, TXB (bidir), TXBN (bidir), VBIAS, VDEC (bidir), XTAL (bidir), XTALN (bidir)

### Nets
C.VDD: R23.1 R26.2
GND: C4.B(-ve) C8.1 C10.B(-ve) C11.1 C18.2 C19.2 C20.2 C21.1 C22.1 C23.1 J4.5(P1) JP1.1 JP2.1 JP3.1 JP4.1 Q2.E(emitter) SW1.4 U3.6(DVSS) U3.10(AVSS) U3.22(AVSS) U3.28(DVSS) U3.39(DVSS) U4.3(GND) U5.10(GND) U6.4(GND) U9.4(GND)
VDD: C19.1 C20.1 C23.2 D4.1(ANODE) J4.10(P1) L2.2 R12.1 R13.1 R15.2 R16.2 R22.2 R25.1 U4.5(VCC) U5.17(A4) U5.20(VCC) U6.7(HOLDN) U6.8(VCC) U9.7(HOLDN) U9.8(VCC)
BOOTDONE: R7.1 U3.41(BOOTDONE) ; port BOOTDONE
BOOTEN1: JP1.2 R12.2 U3.42(BOOTEN1) ; port BOOTEN1
BOOTEN2: JP2.2 R13.2 U3.43(BOOTEN2) ; port BOOTEN2
C.AVDD: C4.A(+ve) JP5.1 L2.1 TP2.TP ; port C.AVDD
C.AVDD.I: C18.1 JP5.2 U3.14(AVDD) ; port C.AVDD.I
C.CSN: J4.4(P1) R23.2 U3.8(CSN/DTRN) U5.18(Y1) ; port C.CSN
C.CTSN: J4.8(P1) U3.30(CTSN) ; port C.CTSN
C.DCDN: J4.1(P1) U3.3(DCDN) ; port C.DCDN
C.DSRN: J4.6(P1) U3.5(DSRN) ; port C.DSRN
C.DVDDI: C21.2 U3.25(DVDD) U3.44(DVDD) ; port C.DVDDI
CDATA: J4.3(P1) U3.7(CDATA/TXD) U5.15(A3) ; port C.CDATA
CSN: U5.2(A1) U5.11(A1) ; port CSN
EP.EPCSN: U5.9(Y1) U5.16(Y2) U6.1(CSN) U9.1(CSN) ; port EP.EPCSN
EP.EPSCLK: U5.7(Y2) U5.14(Y3) U6.6(SCK) U9.6(SCK) ; port EP.EPSCLK
EP.EPSI: U5.5(Y3) U5.12(Y4) U6.5(SI) U9.5(SI) ; port EP.EPSI
EP.WPN: R25.2 U6.3(WPN) U9.3(WPN) ; port EP.WPN
EPCSN: U3.40(EPSCSN) U5.4(A2) ; port EPCSN
EPSCLK: U3.37(EPSCLK) U5.6(A3) ; port EPSCLK
EPSI: U3.36(EPSI) U5.8(A4) ; port EPSI
EVAL: JP3.2 R15.1 SW1.1 U3.29(EVAL) ; port EVAL
EXTLINK45: JP4.2 R16.1 U3.35(EXTLINK45) ; port EXTLINK45
HDN: C22.2 R26.1 R27.1 U3.26(HDN) ; port HDN
IRQN: U3.34(IRQN/RIN) ; port C.IRQN
MEMPROGN: R22.1 U4.2(IN) U5.19(~{OE}) ; port MEMPROGN
NET00000: Q2.C(collector) R9.1
NET00002: D4.2(CATHODE) R9.2
NET00004: Q2.B(base) R7.2
NET00005: J5.3(P1) R27.2
NET00006: U4.4(OUT) U5.1(~{OE})
NET00027: U3.16(RXA2N) ; port RXA2N
NET00028: C6.2 C7.1 R11.2
NET00155: C16.2 R19.2 R21.1 U3.12(RXBN)
NET00156: C16.1 R21.2 U3.11(RXBFB)
NET00157: C12.1 R19.1
RDATA: J4.2(P1) U3.1(RDATA/RXD) U3.38(EPSO) U6.2(SO) U9.2(SO) ; port C.RDATA
RDN: U3.27(RDN) ; port RDN
RLYDRV: U3.2(RDRVN) ; port RLYDRV
RXA: C7.2 R10.1 R11.1 R14.1 U3.15(RXA) ; port RXA
RXAFB: U3.18(RXAFB) ; port RXAFB
RXAN: U3.17(RXAN) ; port RXAN
RXB: J5.8(P1) R28.1 U3.13(RXB) ; port RXB
RXBIN: C12.2 J5.7(P1) ; port RXBIN
SCLK: J4.7(P1) U3.4(SCLK/RTSN) U5.13(A2) ; port C.SCLK
TXA: U3.21(TXA) ; port TXA
TXAN: U3.20(TXAN) ; port TXAN
TXB: J5.6(P1) U3.24(TXB) ; port TXB
TXBN: J5.5(P1) U3.23(TXBN) ; port TXBN
VBIAS: R28.2 U3.19(VBIAS) ; port VBIAS
VDEC: C8.2 U3.9(VDEC) ; port VDEC
XTAL: U3.31(XTAL/CLKIN) ; port XTAL
XTALN: U3.32(XTALN) ; port XTALN
NetC10_A: C10.A(+ve) C11.2 U3.33(VDEC)

Not connected (* = marked no-connect by the designer): C6 1; R10 2; R14 2; SW1 2 3; U4 1; U5 3(Y4)

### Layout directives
net class EQPTSIDE-AN: (no net found under the mark), C.AVDD, C.AVDD.I, NET00027, NET00028, NET00157
net class EQPTSIDE-DIG: C.VDD, GND, NET00000, NET00001, NET00002, NET00004, NET00005, NET00006, VDD

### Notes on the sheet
- HOST->SPI MEMORY
- (near C20) De-coupling for U4 and U5
- An 8 DIP package/socket option
  for the serial memory
- Labels drawn without touching a wire or pin: NET00001

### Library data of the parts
C4 C10 = CAP_TANT_TAJ_B: as C1 on sheet MODEM
C6 C7 = CAP0805: SMT capacitor; Part Number: {Part Number}; WhenFit: SMT_CAP
C8 = CAP0603: as C34 on sheet MODEM
C11 C18 = CAP0603: as C5 on sheet MODEM
C12 = CAP0603: SMT capacitor; Part Number: CAP062; WhenFit: {WhenFit}
C16 = CAP0603: SMT capacitor; Part Number: CAP046; WhenFit: SMT_CAP
C19 C20 = CAP0603: SMT capacitor; Part Number: CAP061; WhenFit: SMT_CAP
C21 C23 = CAP0805: SMT capacitor; Part Number: CAP084; WhenFit: SMT_CAP
C22 = CAP0805: as C25 on sheet LINE IF
D4 = LED0805: LED, 0805 surface mount; Part Number: OPT005
J4 J5 = HEADER_2*5: 10 way, 0.1inch pitch header; Part Number: CON027; WhenFit: PTH
JP1-JP3 = JUMPER2: as JP6 on sheet MODEM
JP4 = JUMPER2: PIN HEADER 2X1; Part Number: CBL004; WhenFit: PTH
JP5 = JUMPER2: PIN HEADER 2X1; Part Number: CON005
L2 = IND0805: as L1 on sheet MODEM
Q2 = BC846: NPN general purpose transistor; Part Number: DSM049; WhenFit: SMT_Other
R7 R22 = CRG0603: as R4 on sheet MODEM
R9 = CRG0603: as R5 on sheet MODEM
R10 R11 = CRG0805: as R3 on sheet MODEM
R12 R13 R15 R16 R25 = CRG0805: Generic SMT resistor, 1%.0.125W.; Part Number: RES091; WhenFit: SMT_RES
R14 = CRG0805: as R1 on sheet MODEM
R19 R21 = CRG0603: as R20 on sheet MODEM
R23 = CRG0805: Generic SMT resistor, 1%.0.125W, RS CRG0805 series.; Part Number: RES109; WhenFit: SMT_RES
R26 = CRG0805: Generic SMT resistor, 1%.0.125W, 0805 series.; Part Number: RES096; WhenFit: SMT_RES
R27 = CRG0805: Generic SMT resistor, 1%.0.125W, 0805 series.; Part Number: RES110; WhenFit: SMT_RES
R28 = CRG0603: as R2 on sheet MODEM
SW1 = OMRONB3SN: Omron B3SN series, low profile, SMT  tactile switch; Part Number: SWI006; WhenFit: AWASH
TP2 = FISH_BEAD: as TP1 on sheet MODEM
U3 = PDSP2_CLCC44_J_SKT: PDSP2 Platform for Telecoms; WhenFit: PTH
U4 = NC7SZ04M5: Tiny Logic single Inverter; Part Number: ICS079; WhenFit: SMT_Other
U5 = 74HC244_SOIC: Octal buffer/line driver; 3-state; Part Number: ICS110; OriginalName: M74HC244M1R; ComponentField6: Power pins are hidden; ComponentField7: Published 8-Jun-2000
U6 = AT25HP512-10PI-2.7: SPI Serial EEPROM 512k; Part Number: {Part Number}; WhenFit: PTH
U9 = M25P10-AVMN: SPI 1Mbit Flash low voltage; Part Number: ICS107; WhenFit: {WhenFit}

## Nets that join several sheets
C.VDD: MODEM (5 pins), LINE IF (R30.2 R32.1), PDSP2 (R23.1 R26.2)
GND: MODEM (28 pins), LINE IF (C25.1 U8.3), PDSP2 (26 pins)
VDD: MODEM (10 pins), PDSP2 (19 pins)
BOOTDONE: MODEM (J3.3), PDSP2 (R7.1 U3.41)
BOOTEN1: MODEM (J3.13), PDSP2 (JP1.2 R12.2 U3.42)
BOOTEN2: MODEM (J3.14), PDSP2 (JP2.2 R13.2 U3.43)
C.CSN: MODEM (R38.2 U2.13), PDSP2 (J4.4 R23.2 U3.8 U5.18)
C.DVDDI: MODEM (C17.2 JP7.1 U2.12), PDSP2 (C21.2 U3.25 U3.44)
CDATA: MODEM (J3.4 U2.14), PDSP2 (J4.3 U3.7 U5.15)
CSN: MODEM (J3.2 R38.1), PDSP2 (U5.2 U5.11)
IRQN: MODEM (J3.10 R24.2 TP8.TP U2.4), PDSP2 (U3.34)
MEMPROGN: MODEM (J3.9), PDSP2 (R22.1 U4.2 U5.19)
NET00027: MODEM (R18.2 U10.1), PDSP2 (U3.16)
RDATA: MODEM (J3.8 U2.16), PDSP2 (5 pins)
RDN: MODEM (J3.5 R4.1), LINE IF (C25.2 R30.1 R33.1 TP11.TP), PDSP2 (U3.27)
RLYDRV: MODEM (J3.7 R8.1 U10.4), LINE IF (U7.2), PDSP2 (U3.2)
RXAFB: MODEM (C13.2 R20.2 TP7.TP U2.8), PDSP2 (U3.18)
RXAIN: MODEM (R17.1 R18.1), LINE IF (C32.1)
RXAN: MODEM (6 pins), PDSP2 (U3.17)
SCLK: MODEM (J3.6 U2.15), PDSP2 (J4.7 U3.4 U5.13)
TXA: MODEM (U2.11), LINE IF (C24.1 R29.2 TP9.TP), PDSP2 (U3.21)
TXAN: MODEM (U2.10), LINE IF (D9.1 T1.3 TP10.TP), PDSP2 (U3.20)
VBIAS: MODEM (C5.2 U2.9), PDSP2 (R28.2 U3.19)
VDEC: MODEM (C9.A C34.2 U2.1), PDSP2 (C8.2 U3.9)
XTAL: MODEM (JP6.2 U2.3), PDSP2 (U3.31)
XTALN: MODEM (C15.2 U2.2 X1.1), PDSP2 (U3.32)

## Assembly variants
_865A: not fitted C1 C4 C6 C7 C8 C10 C11 C18 C22 D4 D5 J4 JP1 JP2 JP3 JP4 JP5 L2 Q2 R1 R3 R7 R9 R10 R11 R12 R13 R14 R15 R16 R19 R21 R22 R23 R25 R26 R27 R28 SW1 TP2 U3 U4 U5 U6 U9
_865A_SMT: not fitted C1 C4 C6 C7 C8 C10 C11 C18 C22 C27 C29 D4 D5 E1 J1 J2 J3 J4 J5 J6 JP1 JP2 JP3 JP4 JP5 JP6 JP7 L2 Q2 R1 R3 R7 R9 R10 R11 R12 R13 R14 R15 R16 R19 R21 R22 R23 R25 R26 R27 R28 SW1 T1 TP1 TP2 TP3 TP4 TP5 TP6 TP7 TP8 TP9 TP10 TP11 U3 U4 U5 U6 U9 X1
_865A_PTH: not fitted C1 C2 C3 C4 C5 C6 C7 C8 C9 C10 C11 C12 C13 C14 C15 C16 C17 C18 C19 C20 C21 C22 C23 C24 C25 C26 C27 C28 C29 C30 C31 C32 C33 C34 D1 D2 D3 D4 D5 D6 D7 D8 D9 J2 J4 JP1 JP2 JP3 JP4 JP5 L1 L2 Q1 Q2 Q3 Q4 R1 R2 R3 R4 R5 R6 R7 R8 R9 R10 R11 R12 R13 R14 R15 R16 R17 R18 R19 R20 R21 R22 R23 R24 R25 R26 R27 R28 R29 R30 R31 R32 R33 R34 R35 R36 R37 R38 R39 R40 SW1 T1 TP2 U1 U2 U3 U4 U5 U6 U7 U8 U9 U10 X1
_865A_AWASH: not fitted C1 C2 C3 C4 C5 C6 C7 C8 C9 C10 C11 C12 C13 C14 C15 C16 C17 C18 C19 C20 C21 C22 C23 C24 C25 C26 C28 C30 C31 C32 C33 C34 D1 D2 D3 D4 D5 D6 D7 D8 D9 E1 J1 J3 J4 J5 J6 JP1 JP2 JP3 JP4 JP5 JP6 JP7 L1 L2 Q1 Q2 Q3 Q4 R1 R2 R3 R4 R5 R6 R7 R8 R9 R10 R11 R12 R13 R14 R15 R16 R17 R18 R19 R20 R21 R22 R23 R24 R25 R26 R27 R28 R29 R30 R31 R32 R33 R34 R35 R36 R37 R38 R39 R40 SW1 TP1 TP2 TP3 TP4 TP5 TP6 TP7 TP8 TP9 TP10 TP11 U1 U2 U3 U4 U5 U6 U7 U8 U9 U10
_865A_SMT_CAP: not fitted C1 C6 C7 C8 C10 C11 C18 C22 C27 C29 D1 D2 D3 D4 D5 D6 D7 D8 D9 E1 J1 J2 J3 J4 J5 J6 JP1 JP2 JP3 JP4 JP5 JP6 JP7 L1 L2 Q1 Q2 Q3 Q4 R1 R2 R3 R4 R5 R6 R7 R8 R9 R10 R11 R12 R13 R14 R15 R16 R17 R18 R19 R20 R21 R22 R23 R24 R25 R26 R27 R28 R29 R30 R31 R32 R33 R34 R35 R36 R37 R38 R39 R40 SW1 T1 TP1 TP2 TP3 TP4 TP5 TP6 TP7 TP8 TP9 TP10 TP11 U1 U2 U3 U4 U5 U6 U7 U8 U9 U10 X1
_865A_SMT_RES: not fitted C1 C2 C3 C4 C5 C6 C7 C8 C9 C10 C11 C12 C13 C14 C15 C16 C17 C18 C19 C20 C21 C22 C23 C24 C25 C26 C27 C28 C29 C30 C31 C32 C33 C34 D1 D2 D3 D4 D5 D6 D7 D8 D9 E1 J1 J2 J3 J4 J5 J6 JP1 JP2 JP3 JP4 JP5 JP6 JP7 L1 L2 Q1 Q2 Q3 Q4 R1 R3 R7 R9 R10 R11 R12 R13 R14 R15 R16 R19 R21 R22 R23 R25 R26 R27 R28 SW1 T1 TP1 TP2 TP3 TP4 TP5 TP6 TP7 TP8 TP9 TP10 TP11 U1 U2 U3 U4 U5 U6 U7 U8 U9 U10 X1
_865A_SMT_OTHER: not fitted C1 C2 C3 C4 C5 C6 C7 C8 C9 C10 C11 C12 C13 C14 C15 C16 C17 C18 C19 C20 C21 C22 C23 C24 C25 C26 C27 C28 C29 C30 C31 C32 C33 C34 D4 D5 E1 J1 J2 J3 J4 J5 J6 JP1 JP2 JP3 JP4 JP5 JP6 JP7 L2 Q2 R1 R2 R3 R4 R5 R6 R7 R8 R9 R10 R11 R12 R13 R14 R15 R16 R17 R18 R19 R20 R21 R22 R23 R24 R25 R26 R27 R28 R29 R30 R31 R32 R33 R34 R35 R36 R37 R38 R39 R40 SW1 T1 TP1 TP2 TP3 TP4 TP5 TP6 TP7 TP8 TP9 TP10 TP11 U3 U4 U5 U6 U9 X1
